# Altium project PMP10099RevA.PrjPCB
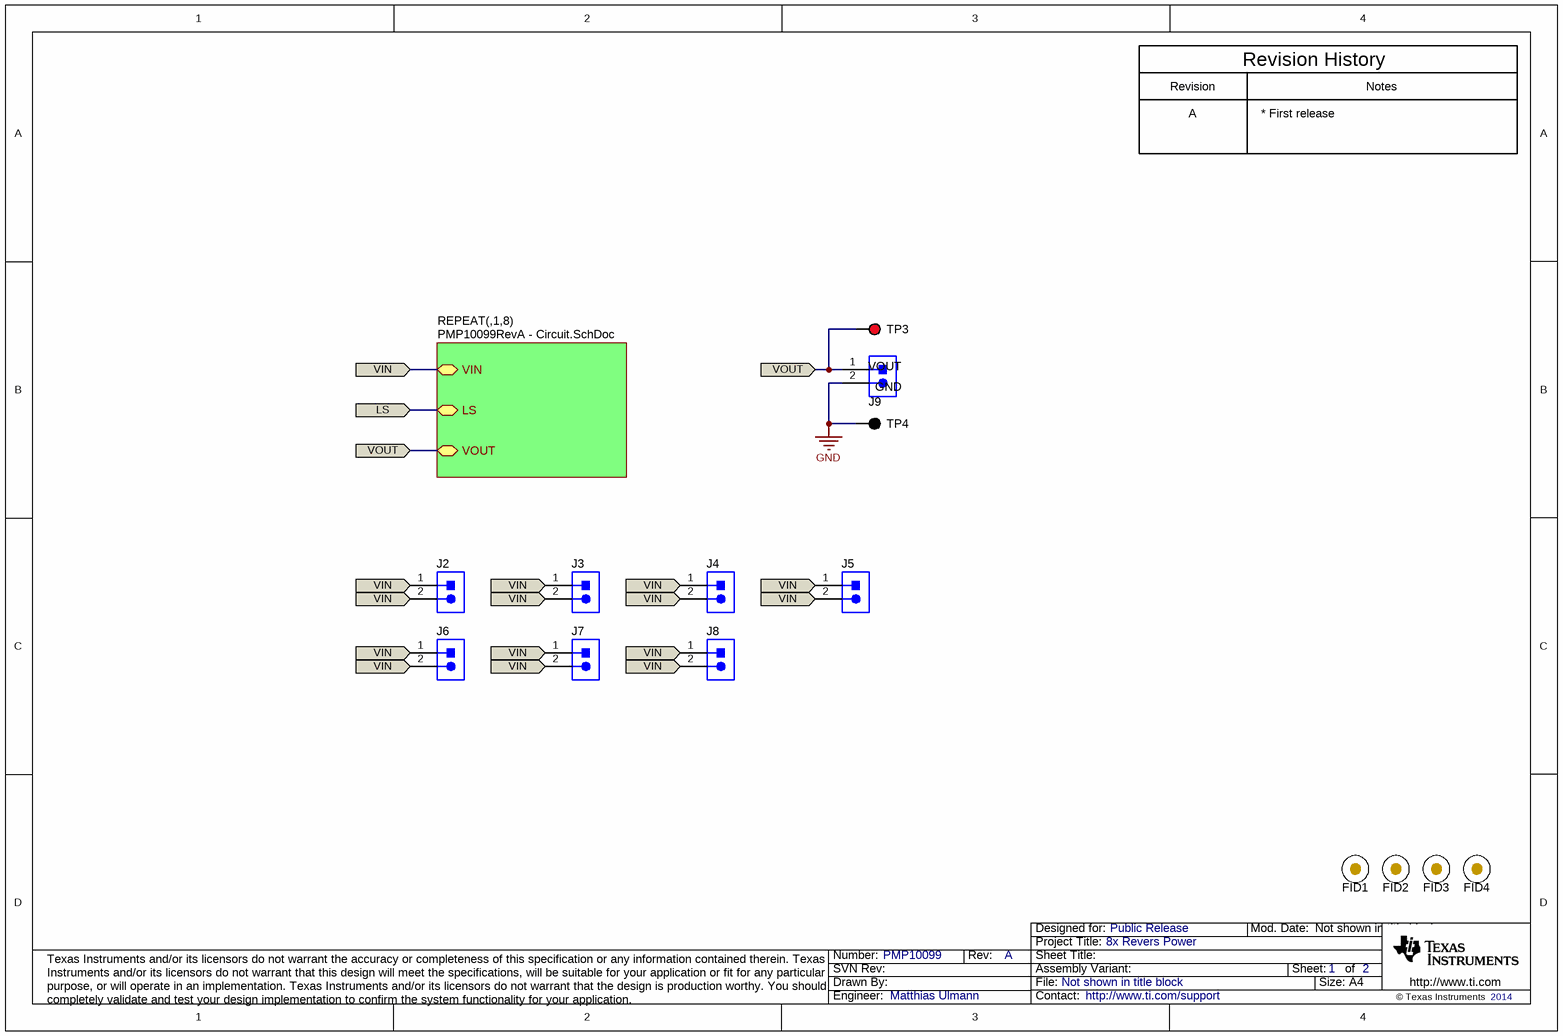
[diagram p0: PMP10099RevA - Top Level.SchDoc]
CopyrightYear: 2014; PCB_Layout: M. Ulmann; PCB_Rev: A; PRJ_Customer: Public Release; PRJ_Engineer: Matthias Ulmann; PRJ_Number: PMP10099; PRJ_Title: 8x Revers Power; SCH_Rev: A; TechSupport: http://www.ti.com/support
2 sheets, 558 parts. Net scope: hierarchical (ports join the sheet entries above them; power ports are global).
Board file: PMP10099RevA.PcbDoc
Sheets:
  PMP10099RevA - Top Level.SchDoc
    1 = PMP10099RevA - Circuit.SchDoc
    2 = PMP10099RevA - Circuit.SchDoc
    3 = PMP10099RevA - Circuit.SchDoc
    4 = PMP10099RevA - Circuit.SchDoc
    5 = PMP10099RevA - Circuit.SchDoc
    6 = PMP10099RevA - Circuit.SchDoc
    7 = PMP10099RevA - Circuit.SchDoc
    8 = PMP10099RevA - Circuit.SchDoc

## Sheet PMP10099RevA - Top Level.SchDoc
size A4; Date: Not shown in title block; ApprovedBy: Not shown in title block; CheckedBy: Not shown in title block; Author: Not shown in title block; CompanyName: Not shown in title block; Engineer: Not shown in title block; Organization: Not shown in title block; Address1: Not shown in title block; Address2: Not shown in title block; Address3: Not shown in title block; Address4: Not shown in title block; DocumentNumber: 1; Revision: Use project parameter SCH_Rev; SheetNumber: 1; SheetTotal: 2; PageSetup: Record=PageOptions|CenterHorizontal=True|CenterVertical=True|PrintScale=0.70|XCorrection=1.00|YCorrection=1.00|PrintKind=0|BorderSize=5000000|LeftOffset=0|BottomOffset=0|Orientation=2|PaperLength=1000|PaperWidth=1000|Scale=100|PaperSource=15|PrintQuality=600|MediaType=1|DitherType=10|PaperKind=A4|PrintScaleMode=1

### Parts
FID1  Fiducial  [Fiducial10-30]  (value not drawn)
FID2  Fiducial  [Fiducial10-30]  (value not drawn)
FID3  Fiducial  [Fiducial10-30]  (value not drawn)
FID4  Fiducial  [Fiducial10-30]  (value not drawn)
J2  PEC02SAAN  [CONN_PEC02SAAN]  (value not drawn)
J3  PEC02SAAN  [CONN_PEC02SAAN]  (value not drawn)
J4  PEC02SAAN  [CONN_PEC02SAAN]  (value not drawn)
J5  PEC02SAAN  [CONN_PEC02SAAN]  (value not drawn)
J6  PEC02SAAN  [CONN_PEC02SAAN]  (value not drawn)
J7  PEC02SAAN  [CONN_PEC02SAAN]  (value not drawn)
J8  PEC02SAAN  [CONN_PEC02SAAN]  (value not drawn)
J9  ED555/2DS  [TERM_BLK_ED555-2DS]  (value not drawn)
TP3  5000  [Keystone5000]  (value not drawn)
TP4  5001  [Keystone5001]  (value not drawn)

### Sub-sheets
REPEAT(,1,8) = PMP10099RevA - Circuit.SchDoc: VOUT, LS, VIN

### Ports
LS, VIN, VOUT

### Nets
GND: J9.2 TP4.1
LS: port LS, sheet REPEAT(,1,8)/LS
VIN: J2.1 J2.2 J3.1 J3.2 J4.1 J4.2 J5.1 J5.2 J6.1 J6.2 J7.1 J7.2 J8.1 J8.2 ; port VIN, sheet REPEAT(,1,8)/VIN
VOUT: J9.1 TP3.1 ; port VOUT, sheet REPEAT(,1,8)/VOUT

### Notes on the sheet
- Revision
- A
- * First release
- Revision History
- Notes
- VOUT
- GND

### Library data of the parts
FID1-FID4 = Fiducial: Fiducial mark.  There is nothing to buy or mount.; SymbolCreator: codlsc
J2-J8 = PEC02SAAN: Header, 100mil, 2x1, Tin, TH; Manufacturer: Sullins Connector Solutions; SymbolCreator: a0412235; U/M: EA
J9 = ED555/2DS: Terminal Block, 6A, 3.5mm Pitch, 2-Pos, TH; Manufacturer: On-Shore Technology; SymbolCreator: a0412235; CompType: Connector; U/M: EA
TP3 = 5000: Test Point, Miniature, Red, TH; Manufacturer: Keystone; CompType: Test Point Loop; U/M: EA
TP4 = 5001: Test Point, Miniature, Black, TH; Manufacturer: Keystone; CompType: Test Point Loop; U/M: EA

## Sheet PMP10099RevA - Circuit.SchDoc
size A3; Date: Not shown in title block; ApprovedBy: Not shown in title block; CheckedBy: Not shown in title block; Author: Not shown in title block; CompanyName: Not shown in title block; Engineer: Not shown in title block; Organization: Not shown in title block; Address1: Not shown in title block; Address2: Not shown in title block; Address3: Not shown in title block; Address4: Not shown in title block; DocumentNumber: 2; Revision: Use project parameter SCH_Rev; SheetNumber: 2; SheetTotal: 2; PageSetup: Record=PageOptions|CenterHorizontal=True|CenterVertical=True|PrintScale=0.70|XCorrection=1.00|YCorrection=1.00|PrintKind=0|BorderSize=5000000|LeftOffset=0|BottomOffset=0|Orientation=2|PaperLength=1000|PaperWidth=1000|Scale=100|PaperSource=15|PrintQuality=600|MediaType=1|DitherType=10|PaperKind=A4|PrintScaleMode=1
Used 8 times, as channels 1, 2, 3, 4, 5, 6, 7, 8. Parts and nets are listed once, with the designators drawn on the sheet.
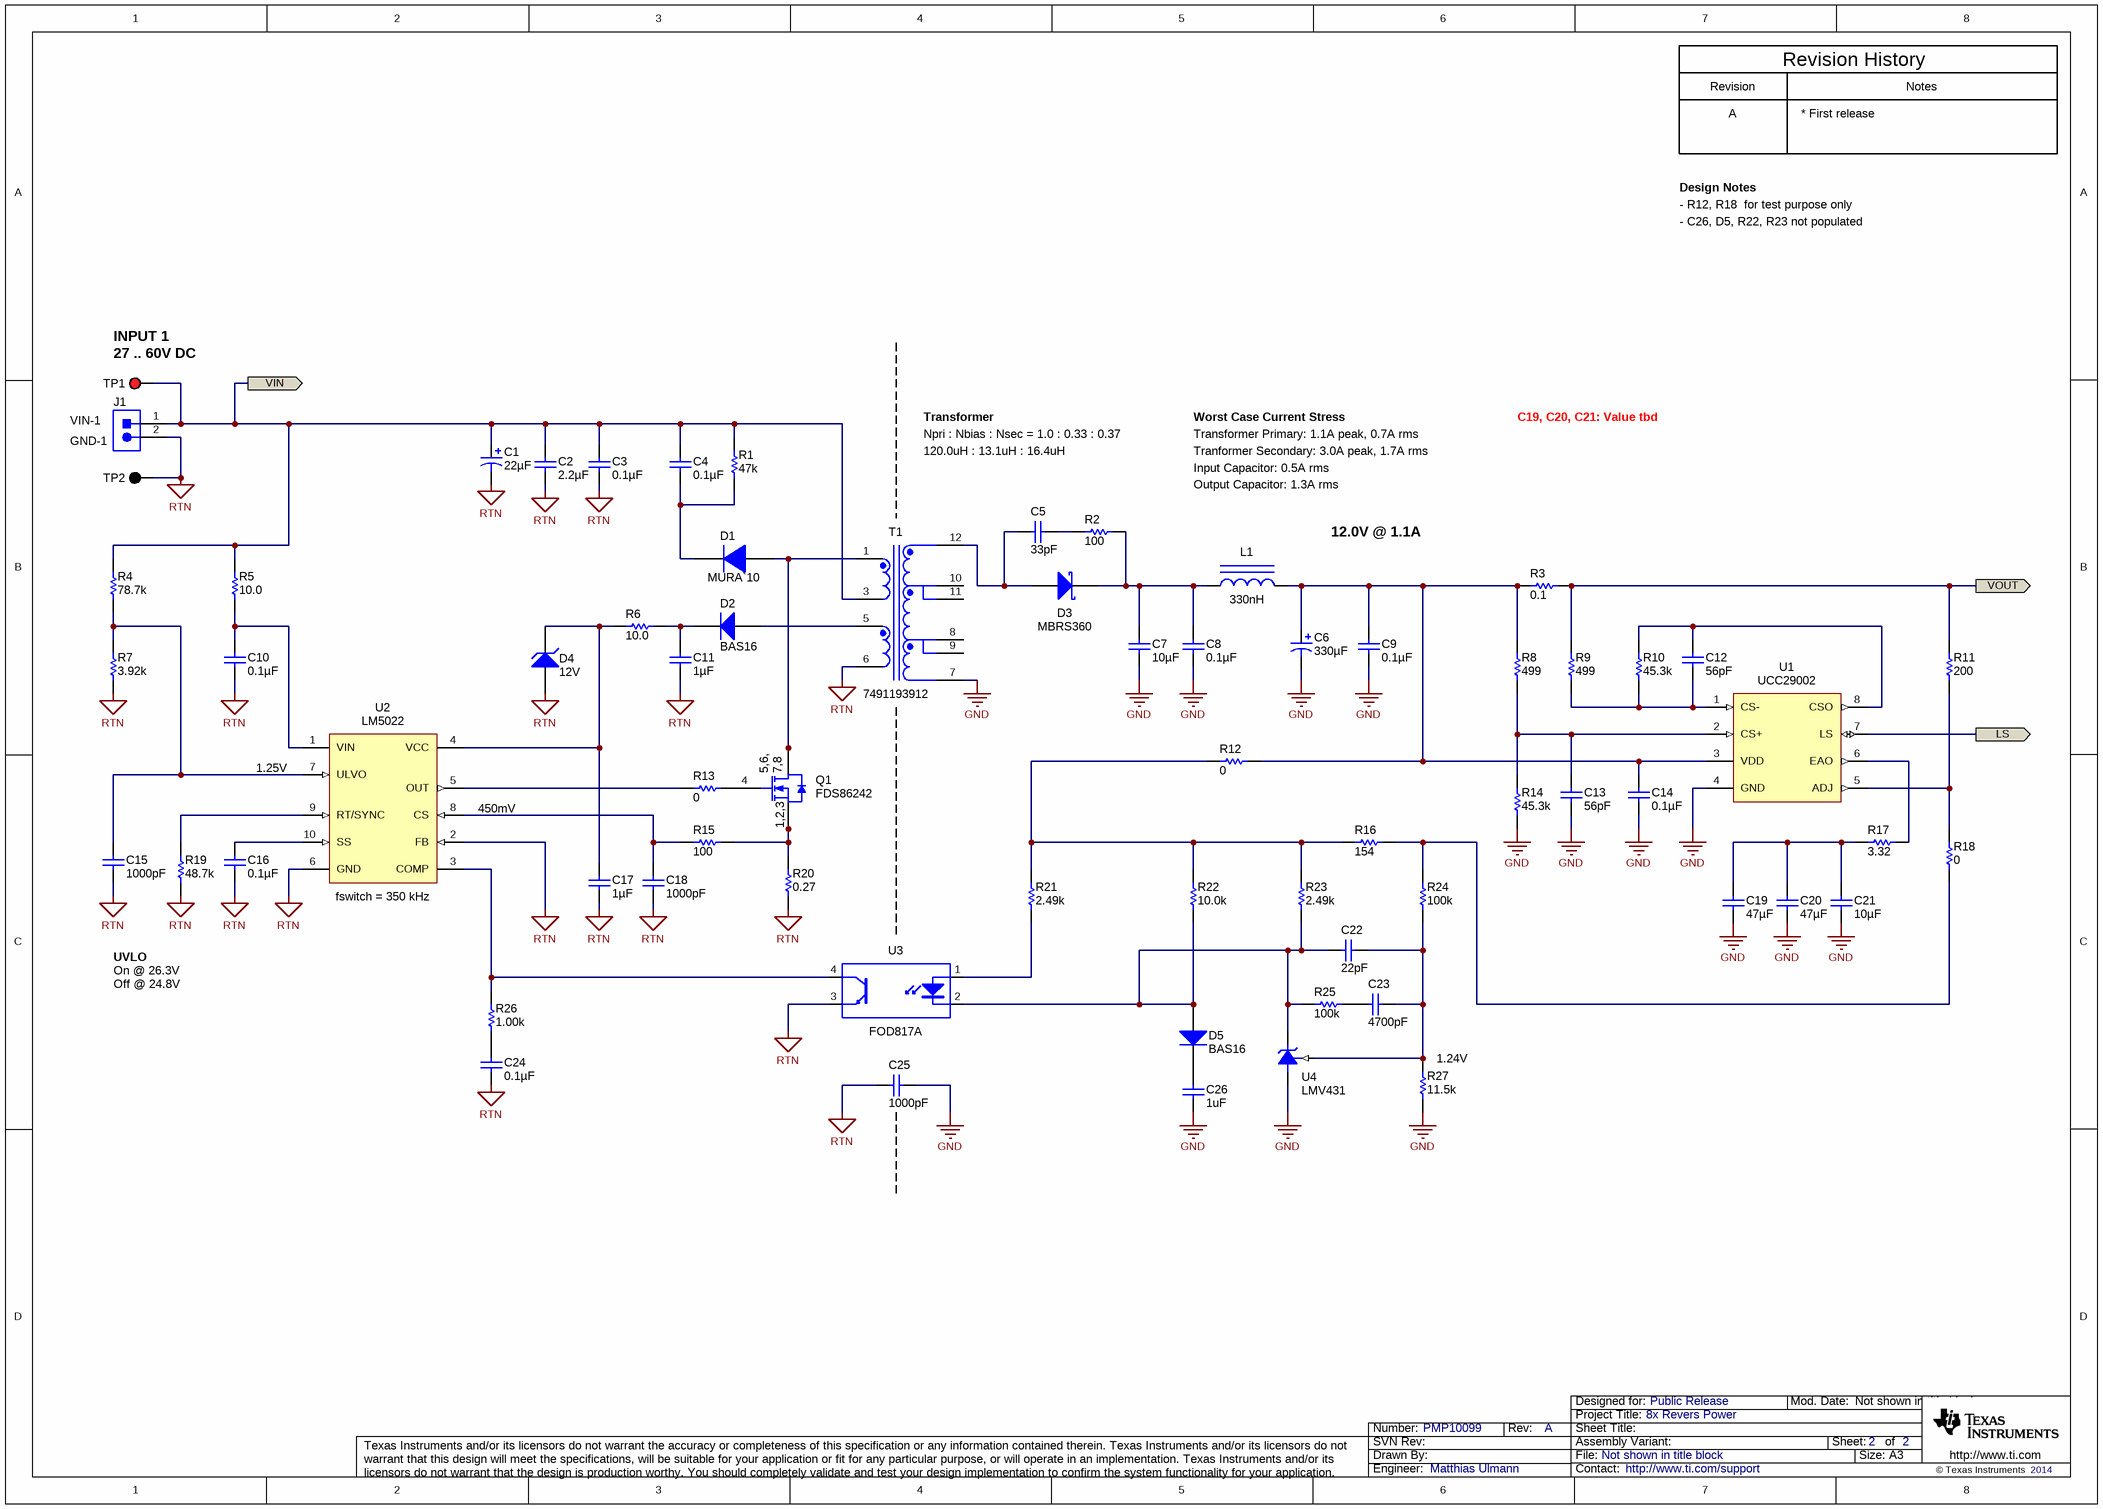
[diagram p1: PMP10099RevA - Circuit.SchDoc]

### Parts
C1  ValueDisplayed: 22µF  [SM_RADIAL_F]  (hidden comment: EEE-FK1K220P)
C2  ValueDisplayed: 2.2µF  [1210]  (hidden comment: GRM32ER72A225KA35L)
C3  ValueDisplayed: 0.1µF  [0603]  (hidden comment: GCM188R71H104KA57D)
C4  ValueDisplayed: 0.1µF  [0805_HV]  (hidden comment: HMK212B7104KG-T)
C5  ValueDisplayed: 33pF  [0805_HV]  (hidden comment: GRM2195C2A330JZ01D)
C6  ValueDisplayed: 330µF  [SM_RADIAL_F]  (hidden comment: EEE-FK1C331P)
C7  ValueDisplayed: 10µF  [1206]  (hidden comment: GRM31CR71E106KA12L)
C8  ValueDisplayed: 0.1µF  [0603]  (hidden comment: GCM188R71H104KA57D)
C9  ValueDisplayed: 0.1µF  [0603]  (hidden comment: GCM188R71H104KA57D)
C10  ValueDisplayed: 0.1µF  [0805_HV]  (hidden comment: HMK212B7104KG-T)
C11  ValueDisplayed: 1µF  [0603]  (hidden comment: GRM188R71E105KA12D)
C12  ValueDisplayed: 56pF  [0603]  (hidden comment: GRM1885C1H560JA01D)
C13  ValueDisplayed: 56pF  [0603]  (hidden comment: GRM1885C1H560JA01D)
C14  ValueDisplayed: 0.1µF  [0603]  (hidden comment: GCM188R71H104KA57D)
C15  ValueDisplayed: 1000pF  [0603]  (hidden comment: GRM188R71H102KA01D)
C16  ValueDisplayed: 0.1µF  [0603]  (hidden comment: GCM188R71H104KA57D)
C17  ValueDisplayed: 1µF  [0603]  (hidden comment: GRM188R71E105KA12D)
C18  ValueDisplayed: 1000pF  [0603]  (hidden comment: GRM188R71H102KA01D)
C19  ValueDisplayed: 47µF  [1210]  (hidden comment: GRM32ER70J476KE20L)
C20  ValueDisplayed: 47µF  [1210]  (hidden comment: GRM32ER70J476KE20L)
C21  ValueDisplayed: 10µF  [0805_140]  (hidden comment: GRM21BR71A106KE51K)
C22  ValueDisplayed: 22pF  [0603]  (hidden comment: GRM1885C1H220JA01D)
C23  ValueDisplayed: 4700pF  [0603]  (hidden comment: GRM188R71H472KA01D)
C24  ValueDisplayed: 0.1µF  [0603]  (hidden comment: GCM188R71H104KA57D)
C25  ValueDisplayed: 1000pF  [1812]  (hidden comment: 1812GC102KA1)
C26  ValueDisplayed: 1uF  [0603]  (hidden comment: GRM188R71E105KA12D)
D1  MURA`10  [SMA]
D2  BAS16  [SOT-23]
D3  MBRS360  [SMC]
D4  value 12V  [sod-323]  (hidden comment: BZX384-C12,115)
D5  BAS16  [SOT-23]
J1  ED555/2DS  [TERM_BLK_ED555-2DS]  (value not drawn)
L1  330nH  [WE-MAPI_3020]
Q1  FDS86242  [SOIC-8]
R1  ValueDisplayed: 47k  [1206]  (hidden comment: CRCW120647K0JNEA)
R2  value 100  [0805_HV]  (hidden comment: CRCW0805100RJNEA)
R3  ValueDisplayed: 0.1  [1206]  (hidden comment: ERJ-8RSJR10V)
R4  value 78.7k  [0805_HV]  (hidden comment: CRCW080578K7FKEA)
R5  value 10.0  [0805_HV]  (hidden comment: CRCW080510R0FKEA)
R6  ValueDisplayed: 10.0  [0603]  (hidden comment: CRCW060310R0FKEA)
R7  value 3.92k  [0805_HV]  (hidden comment: CRCW08053K92FKEA)
R8  ValueDisplayed: 499  [0603]  (hidden comment: CRCW0603499RFKEA)
R9  ValueDisplayed: 499  [0603]  (hidden comment: CRCW0603499RFKEA)
R10  ValueDisplayed: 45.3k  [0603]  (hidden comment: CRCW060345K3FKEA)
R11  ValueDisplayed: 200  [0603]  (hidden comment: CRCW0603200RFKEA)
R12  ValueDisplayed: 0  [0603]  (hidden comment: CRCW06030000Z0EA)
R13  ValueDisplayed: 0  [0603]  (hidden comment: CRCW06030000Z0EA)
R14  ValueDisplayed: 45.3k  [0603]  (hidden comment: CRCW060345K3FKEA)
R15  ValueDisplayed: 100  [0603]  (hidden comment: CRCW0603100RFKEA)
R16  ValueDisplayed: 154  [0603]  (hidden comment: CRCW0603154RFKEA)
R17  ValueDisplayed: 3.32  [0603]  (hidden comment: CRCW06033R32FKEA)
R18  ValueDisplayed: 0  [0603]  (hidden comment: CRCW06030000Z0EA)
R19  ValueDisplayed: 48.7k  [0603]  (hidden comment: CRCW060348K7FKEA)
R20  ValueDisplayed: 0.27  [1206]  (hidden comment: ERJ-8RQFR27V)
R21  ValueDisplayed: 2.49k  [0603]  (hidden comment: CRCW06032K49FKEA)
R22  ValueDisplayed: 10.0k  [0603]  (hidden comment: CRCW060310K0FKEA)
R23  ValueDisplayed: 2.49k  [0603]  (hidden comment: CRCW06032K49FKEA)
R24  ValueDisplayed: 100k  [0603]  (hidden comment: CRCW0603100KFKEA)
R25  ValueDisplayed: 100k  [0603]  (hidden comment: CRCW0603100KFKEA)
R26  ValueDisplayed: 1.00k  [0603]  (hidden comment: CRCW06031K00FKEA)
R27  ValueDisplayed: 11.5k  [0603]  (hidden comment: CRCW060311K5FKEA)
T1  7491193912  [WURTH_7491193912]
TP1  5000  [Keystone5000]  (value not drawn)
TP2  5001  [Keystone5001]  (value not drawn)
U1  UCC29002  [DGK0008A_N]
U2  LM5022  [MUB10A_N]
U3  FOD817A  [N04C]
U4  LMV431  [MF03A_N]

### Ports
LS, VIN, VOUT

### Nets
GND: C6.2(-) C7.2 C8.2 C9.2 C13.2 C14.2 C19.2 C20.2 C21.2 C25.1 C26.2 R14.1 R27.1 T1.7 U1.4(GND) U4.3(A)
RTN: C1.2(-) C2.2 C3.2 C10.2 C11.2 C15.2 C16.2 C17.2 C18.2 C24.2 C25.2 D4.2(A) J1.2 R7.1 R19.1 R20.1 T1.6 TP2.1 U2.2(FB) U2.6(GND) U3.3(E)
LS: U1.7(LS) ; port LS
VIN: C1.1(+) C2.1 C3.1 C4.1 J1.1 R1.2 R4.2 R5.2 T1.3 TP1.1 ; port VIN
VOUT: R3.2 R9.2 R11.2 ; port VOUT
NetC4_2: C4.2 D1.1(K) R1.1
NetC5_1: C5.1 R2.1
NetC5_2: C5.2 D3.2(A) T1.12
NetC6_1: C6.1(+) C9.1 C14.1 L1.2 R3.1 R8.2 R12.2 U1.3(VDD)
NetC7_1: C7.1 C8.1 D3.1(K) L1.1 R2.2
NetC10_1: C10.1 R5.1 U2.1(VIN)
NetC11_1: C11.1 D2.3(K) R6.2
NetC12_1: C12.1 R10.2 U1.8(CSO)
NetC12_2: C12.2 R9.1 R10.1 U1.1(CS-)
NetC13_1: C13.1 R8.1 R14.2 U1.2(CS+)
NetC15_1: C15.1 R4.1 R7.2 U2.7(ULVO)
NetC16_1: C16.1 U2.10(SS)
NetC17_1: C17.1 D4.1(K) R6.1 U2.4(VCC)
NetC18_1: C18.1 R15.1 U2.8(CS)
NetC19_1: C19.1 C20.1 C21.1 R17.1
NetC22_1: C22.1 D5.1(A) R22.2 R23.1 R25.2 U3.2(K) U4.2(K)
NetC22_2: C22.2 C23.2 R24.1 R27.2 U4.1(REF)
NetC23_1: C23.1 R25.1
NetC24_1: C24.1 R26.1
NetC26_1: C26.1 D5.3(K)
NetD1_2: D1.2(A) Q1.5(D) Q1.6(D) Q1.7(D) Q1.8(D) T1.1
NetD2_1: D2.1(A) T1.5
NetQ1_1: Q1.1(S) Q1.2(S) Q1.3(S) R15.2 R20.2
NetQ1_4: Q1.4(G) R13.2
NetR11_1: R11.1 R18.2 U1.5(ADJ)
NetR12_1: R12.1 R16.1 R21.2 R22.1 R23.2
NetR13_1: R13.1 U2.5(OUT)
NetR16_2: R16.2 R18.1 R24.2
NetR17_2: R17.2 U1.6(EAO)
NetR19_2: R19.2 U2.9(RT/SYNC)
NetR21_1: R21.1 U3.1(A)
NetR26_2: R26.2 U2.3(COMP) U3.4(C)

Not connected (* = marked no-connect by the designer): T1 8 9 10 11

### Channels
1: designators end in _A; ports LS=LS VIN=VIN VOUT=VOUT
2: designators end in _B; ports LS=LS VIN=VIN VOUT=VOUT
3: designators end in _C; ports LS=LS VIN=VIN VOUT=VOUT
4: designators end in _D; ports LS=LS VIN=VIN VOUT=VOUT
5: designators end in _E; ports LS=LS VIN=VIN VOUT=VOUT
6: designators end in _F; ports LS=LS VIN=VIN VOUT=VOUT
7: designators end in _G; ports LS=LS VIN=VIN VOUT=VOUT
8: designators end in _H; ports LS=LS VIN=VIN VOUT=VOUT

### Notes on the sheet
- Revision
- A
- * First release
- Revision History
- Notes
- Design Notes
- - R12, R18  for test purpose only
- - C26, D5, R22, R23 not populated
- (near TP1) INPUT 1
- (near TP1) 27 .. 60V DC
- VIN-1
- GND-1
- Transformer
- Npri : Nbias : Nsec = 1.0 : 0.33 : 0.37
- 120.0uH : 13.1uH : 16.4uH
- Worst Case Current Stress
- Transformer Primary: 1.1A peak, 0.7A rms
- Tranformer Secondary: 3.0A peak, 1.7A rms
- C19, C20, C21: Value tbd
- Input Capacitor: 0.5A rms
- Output Capacitor: 1.3A rms
- 12.0V @ 1.1A
- (near U2) 1.25V
- (near U2) 450mV
- (near U2) fswitch = 350 kHz
- On @ 26.3V
- Off @ 24.8V
- UVLO
- (near R27) 1.24V

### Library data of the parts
C1 = EEE-FK1K220P: CAP, AL, 22 µF, 80 V, +/- 20%, 1.3 ohm, SMD; Manufacturer: Panasonic; Polarized: Y; CompType: Capacitor; Value: 22uF; U/M: EA; Cap_F: 0.000022; Tolerance_%: 20; Value1: 1.3 ohm; VDC_V: 80; Value2: 80V; ESR_ohm: 1.3; IRMS_A: 0.13; TaMin_C: -55; TaMax_C: 105; Cap_Case: F
C2 = GRM32ER72A225KA35L: CAP, CERM, 2.2 µF, 100 V, +/- 10%, X7R, 1210; Manufacturer: MuRata; Polarized: N; CompType: Capacitor; Value: 2.2uF; U/M: EA; Cap_F: 0.0000022; Tolerance_%: 10; ESR_ohm: 0.007; Value1: 0.007 ohm; VDC_V: 100; Value2: 100V; IRMS_A: 4.4; TaMin_C: -55; TaMax_C: 125
C3 C8 C9 C14 C16 C24 = GCM188R71H104KA57D: CAP, CERM, 0.1 µF, 50 V, +/- 10%, X7R, 0603; Manufacturer: MuRata; Polarized: N; CompType: Capacitor; Value: 0.1uF; U/M: EA; Cap_F: 0.0000001; Tolerance_%: 10; ESR_ohm: 0.02; Value1: 0.02 ohm; VDC_V: 50; Value2: 50V; IRMS_A: 1.84; TaMin_C: -55; TaMax_C: 125
C4 C10 = HMK212B7104KG-T: CAP, CERM, 0.1 µF, 100 V, +/- 10%, X7R, 0805; Manufacturer: Taiyo Yuden; Polarized: N; CompType: Capacitor; Value: 0.1uF; U/M: EA; Cap_F: 0.0000001; Tolerance_%: 10; Value1: Unknown; VDC_V: 100; Value2: 100V; TaMin_C: -55; TaMax_C: 125; Cap_Case: 0805
C5 = GRM2195C2A330JZ01D: CAP, CERM, 33 pF, 100 V, +/- 5%, C0G/NP0, 0805; Manufacturer: MuRata; Polarized: N; CompType: Capacitor; Value: 33pF; U/M: EA; Cap_F: 0.000000000033; Tolerance_%: 5; Value1: Unknown; VDC_V: 100; Value2: 100V; TaMin_C: -55; TaMax_C: 125; Cap_Case: 0805
C6 = EEE-FK1C331P: CAP, AL, 330 µF, 16 V, +/- 20%, 0.16 ohm, SMD; Manufacturer: Panasonic; Polarized: Y; CompType: Capacitor; Value: 330uF; U/M: EA; Cap_F: 0.00033; Tolerance_%: 20; VDC_V: 16; Value2: 16V; ESR_ohm: 0.16; IRMS_A: 0.6; TaMin_C: -55; TaMax_C: 105; Cap_Case: F
C7 = GRM31CR71E106KA12L: CAP, CERM, 10 µF, 25 V, +/- 10%, X7R, 1206; Manufacturer: MuRata; Polarized: N; CompType: Capacitor; Value: 10uF; U/M: EA; Cap_F: 0.00001; Tolerance_%: 10; Value1: Unknown; VDC_V: 25; Value2: 25V; TaMin_C: -55; TaMax_C: 125; Cap_Case: 2220
C11 C17 C26 = GRM188R71E105KA12D: CAP, CERM, 1 µF, 25 V, +/- 10%, X7R, 0603; Manufacturer: MuRata; Polarized: N; CompType: Capacitor; Value: 1uF; U/M: EA; Cap_F: 0.000001; Tolerance_%: 10; Value1: Unknown; VDC_V: 25; Value2: 25V; TaMin_C: -55; TaMax_C: 125
C12 C13 = GRM1885C1H560JA01D: CAP, CERM, 56 pF, 50 V, +/- 5%, C0G/NP0, 0603; Manufacturer: MuRata; Polarized: N; CompType: Capacitor; Value: 56pF; U/M: EA; Cap_F: 0.000000000056; Tolerance_%: 5; Value1: Unknown; VDC_V: 50; Value2: 50V; TaMin_C: -55; TaMax_C: 125
C15 C18 = GRM188R71H102KA01D: CAP, CERM, 1000 pF, 50 V, +/- 10%, X7R, 0603; Manufacturer: MuRata; Polarized: N; CompType: Capacitor; Value: 1000pF; U/M: EA; Cap_F: 0.000000001; Tolerance_%: 10; Value1: Unknown; VDC_V: 50; Value2: 50V; TaMin_C: -55; TaMax_C: 125
C19 C20 = GRM32ER70J476KE20L: CAP, CERM, 47 µF, 6.3 V, +/- 10%, X7R, 1210; Manufacturer: MuRata; Polarized: N; CompType: Capacitor; Value: 47uF; U/M: EA; Cap_F: 0.000047; Tolerance_%: 10; Value1: Unknown; VDC_V: 6.3; Value2: 6.3V; TaMin_C: -55; TaMax_C: 125
C21 = GRM21BR71A106KE51K: CAP, CERM, 10 µF, 10 V, +/- 10%, X7R, 0805_140; Manufacturer: MuRata; Polarized: N; CompType: Capacitor; Value: 10uF; U/M: EA; Cap_F: 0.00001; Tolerance_%: 10; Value1: Unknown; Value2: 10V; TaMin_C: -55; TaMax_C: 125; Cap_Case: 0805
C22 = GRM1885C1H220JA01D: CAP, CERM, 22 pF, 50 V, +/- 5%, C0G/NP0, 0603; Manufacturer: MuRata; Polarized: N; CompType: Capacitor; Value: 22pF; U/M: EA; Cap_F: 0.000000000022; Tolerance_%: 5; Value1: Unknown; VDC_V: 50; Value2: 50V; TaMin_C: -55; TaMax_C: 125
C23 = GRM188R71H472KA01D: CAP, CERM, 4700 pF, 50 V, +/- 10%, X7R, 0603; Manufacturer: MuRata; Polarized: N; CompType: Capacitor; Value: 4700pF; U/M: EA; Cap_F: 0.0000000047; Tolerance_%: 10; Value1: Unknown; VDC_V: 50; Value2: 50V; TaMin_C: -55; TaMax_C: 125
C25 = 1812GC102KA1: CAP, CERM, 1000 pF, 2000 V, +/- 10%, X7R, 1812; Manufacturer: AVX; Polarized: N; CompType: Capacitor; Value: 1000pF; U/M: EA; Cap_F: 0.000000001; Tolerance_%: 10; Value1: Unknown; VDC_V: 2000; Value2: 2000V; TaMin_C: -55; TaMax_C: 125
D1 = MURA120T3G: Diode, Ultrafast, 200 V, 1 A, SMA; Manufacturer: ON Semiconductor; U/M: EA; Vf_V: 0.0875; Value: 200V; Value1: 1A; Value2: 0.0875V; Io_A: 1; Vr_V: 200; TJmax_C: 175
D2 D5 = BAS16-7-F: Diode, Ultrafast, 75 V, 0.3 A, SOT-23; Manufacturer: Diodes Inc.; U/M: EA; Vf_V: 1.125; Value: 75V; Value1: 0.3A; Value2: 1.125V; Io_A: 0.3; Vr_V: 75
D3 = MBRS340T3G: Diode, Schottky, 60 V, 3 A, SMC; PartNumber: MBRS360T3G; Manufacturer: ON Semiconductor; U/M: EA; Vf_V: 0.525; Value: 60V; Value1: 3A; Value2: 0.525V; Io_A: 3; Vr_V: 60; TJmax_C: 125; RJC_CperW: 11
D4 = BZX384-C12,115: Diode, Zener, 12 V, 300 mW, SOD-323; Manufacturer: NXP Semiconductor; SymbolCreator: a0412235; U/M: EA; Power_W: 0.3; Vz_V: 12; Value1: 0.3W; RJA_CperW: 415
J1 = ED555/2DS: as J9 on sheet PMP10099RevA - Top Level
L1 = 744383360033: Inductor, 330 nH, 5.5 A, 0.014 ohm, SMD; Manufacturer: Wurth Elektronik eiSos; Ind_H: 330.0E-9; Imax_A: 5.5; Irms: 5.5A @ 40C rise; Isat: 8.3A @ 20% inductance drop; DCR_ohm: 0.014; Value2: 5.5A
Q1 = FDS86242: MOSFET, N-CH, 150 V, 4.1 A, SOIC-8; Manufacturer: Fairchild Semiconductor; Alternate Manufacturer: None; U/M: EA; ChType: N; Value: 150V; VdsMax_V: 150; Value1: 0.067 ohm; Rdson45_ohm: 0.067; Value2: 13 nC; QgTyp_nC: 13; Vgs_V: 4; IdsMax_A: 4.1
R1 = CRCW120647K0JNEA: RES, 47 k, 5%, 0.25 W, 1206; Manufacturer: Vishay-Dale; CompType: Resistor; Value: 47k; Res_ohm: 47000; Value_Code: 47k0; Tolerance_%: 5; Power_W: 0.25; Value2: 0.25W; VDC_V: 200; TempCo: 200 ppm/C; EIA_Code: E24; U/M: EA
R2 = CRCW0805100RJNEA: RES, 100 ohm, 5%, 0.125W, 0805; Manufacturer: Vishay-Dale; CompType: Resistor; Value_Code: 100R; Tolerance_%: 5; Power_W: 0.125; VDC_V: 150; TempCo: 200 ppm/C; EIA_Code: E24; U/M: EA
R3 = ERJ-8RSJR10V: RES, 0.1, 5%, 0.25 W, 1206; Manufacturer: Panasonic; CompType: Resistor; Value: 0.1; Value_Code: R100; Tolerance_%: 5; Power_W: 0.25; Value2: 0.25W; TempCo: 250 ppm/C; EIA_Code: E24; U/M: EA
R4 = CRCW080578K7FKEA: RES, 78.7k ohm, 1%, 0.125W, 0805; Manufacturer: Vishay-Dale; CompType: Resistor; Res_ohm: 78700; Value_Code: 78k7; Tolerance_%: 1; Power_W: 0.125; VDC_V: 150; TempCo: 100 ppm/C; EIA_Code: E96; U/M: EA
R5 = CRCW080510R0FKEA: RES, 10.0 ohm, 1%, 0.125W, 0805; Manufacturer: Vishay-Dale; CompType: Resistor; Res_ohm: 10; Value_Code: 10R0; Tolerance_%: 1; Power_W: 0.125; VDC_V: 150; TempCo: 100 ppm/C; EIA_Code: E96; U/M: EA
R6 = CRCW060310R0FKEA: RES, 10.0, 1%, 0.1 W, 0603; Manufacturer: Vishay-Dale; CompType: Resistor; Value: 10.0; Res_ohm: 10; Value_Code: 10R0; Tolerance_%: 1; Power_W: 0.1; Value2: 0.1W; VDC_V: 75; TempCo: 100 ppm/C; EIA_Code: E96; U/M: EA
R7 = CRCW08053K92FKEA: RES, 3.92k ohm, 1%, 0.125W, 0805; Manufacturer: Vishay-Dale; CompType: Resistor; Res_ohm: 3920; Value_Code: 3k92; Tolerance_%: 1; Power_W: 0.125; VDC_V: 150; TempCo: 100 ppm/C; EIA_Code: E96; U/M: EA
R8 R9 = CRCW0603499RFKEA: RES, 499, 1%, 0.1 W, 0603; Manufacturer: Vishay-Dale; CompType: Resistor; Value: 499; Value_Code: 499R; Tolerance_%: 1; Power_W: 0.1; Value2: 0.1W; VDC_V: 75; TempCo: 100 ppm/C; EIA_Code: E96; U/M: EA
R10 R14 = CRCW060345K3FKEA: RES, 45.3 k, 1%, 0.1 W, 0603; Manufacturer: Vishay-Dale; CompType: Resistor; Value: 45.3k; Res_ohm: 45300; Value_Code: 45k3; Tolerance_%: 1; Power_W: 0.1; Value2: 0.1W; VDC_V: 75; TempCo: 100 ppm/C; EIA_Code: E96; U/M: EA
R11 = CRCW0603200RFKEA: RES, 200, 1%, 0.1 W, 0603; Manufacturer: Vishay-Dale; CompType: Resistor; Value: 200; Value_Code: 200R; Tolerance_%: 1; Power_W: 0.1; Value2: 0.1W; VDC_V: 75; TempCo: 100 ppm/C; EIA_Code: E96; U/M: EA
R12 R13 R18 = CRCW06030000Z0EA: RES, 0, 5%, 0.1 W, 0603; Manufacturer: Vishay-Dale; CompType: Resistor; Value: 0; Value_Code: 0000; Tolerance_%: 5; Power_W: 0.1; Value2: 0.1W; VDC_V: 75; TempCo: 200 ppm/C; EIA_Code: E24; U/M: EA
R15 = CRCW0603100RFKEA: RES, 100, 1%, 0.1 W, 0603; Manufacturer: Vishay-Dale; CompType: Resistor; Value: 100; Value_Code: 100R; Tolerance_%: 1; Power_W: 0.1; Value2: 0.1W; VDC_V: 75; TempCo: 100 ppm/C; EIA_Code: E96; U/M: EA
R16 = CRCW0603154RFKEA: RES, 154, 1%, 0.1 W, 0603; Manufacturer: Vishay-Dale; CompType: Resistor; Value: 154; Value_Code: 154R; Tolerance_%: 1; Power_W: 0.1; Value2: 0.1W; VDC_V: 75; TempCo: 100 ppm/C; EIA_Code: E96; U/M: EA
R17 = CRCW06033R32FKEA: RES, 3.32, 1%, 0.1 W, 0603; Manufacturer: Vishay-Dale; CompType: Resistor; Value: 3.32; Value_Code: 3R32; Tolerance_%: 1; Power_W: 0.1; Value2: 0.1W; VDC_V: 75; TempCo: 100 ppm/C; EIA_Code: E96; U/M: EA
R19 = CRCW060348K7FKEA: RES, 48.7 k, 1%, 0.1 W, 0603; Manufacturer: Vishay-Dale; CompType: Resistor; Value: 48.7k; Res_ohm: 48700; Value_Code: 48k7; Tolerance_%: 1; Power_W: 0.1; Value2: 0.1W; VDC_V: 75; TempCo: 100 ppm/C; EIA_Code: E96; U/M: EA
R20 = ERJ-8RQFR27V: RES, 0.27, 1%, 0.25 W, 1206; Manufacturer: Panasonic; CompType: Resistor; Value: 0.27; Value_Code: R270; Tolerance_%: 1; Power_W: 0.25; Value2: 0.25W; TempCo: 250 ppm/C; EIA_Code: E96; U/M: EA
R21 R23 = CRCW06032K49FKEA: RES, 2.49 k, 1%, 0.1 W, 0603; Manufacturer: Vishay-Dale; CompType: Resistor; Value: 2.49k; Res_ohm: 2490; Value_Code: 2k49; Tolerance_%: 1; Power_W: 0.1; Value2: 0.1W; VDC_V: 75; TempCo: 100 ppm/C; EIA_Code: E96; U/M: EA
R22 = CRCW060310K0FKEA: RES, 10.0 k, 1%, 0.1 W, 0603; Manufacturer: Vishay-Dale; CompType: Resistor; Value: 10.0k; Res_ohm: 10000; Value_Code: 10k0; Tolerance_%: 1; Power_W: 0.1; Value2: 0.1W; VDC_V: 75; TempCo: 100 ppm/C; EIA_Code: E96; U/M: EA
R24 R25 = CRCW0603100KFKEA: RES, 100 k, 1%, 0.1 W, 0603; Manufacturer: Vishay-Dale; CompType: Resistor; Value: 100k; Res_ohm: 100000; Tolerance_%: 1; Power_W: 0.1; Value2: 0.1W; VDC_V: 75; TempCo: 100 ppm/C; EIA_Code: E96; U/M: EA
R26 = CRCW06031K00FKEA: RES, 1.00 k, 1%, 0.1 W, 0603; Manufacturer: Vishay-Dale; CompType: Resistor; Value: 1.00k; Res_ohm: 1000; Value_Code: 1k00; Tolerance_%: 1; Power_W: 0.1; Value2: 0.1W; VDC_V: 75; TempCo: 100 ppm/C; EIA_Code: E96; U/M: EA
R27 = CRCW060311K5FKEA: RES, 11.5 k, 1%, 0.1 W, 0603; Manufacturer: Vishay-Dale; CompType: Resistor; Value: 11.5k; Res_ohm: 11500; Value_Code: 11k5; Tolerance_%: 1; Power_W: 0.1; Value2: 0.1W; VDC_V: 75; TempCo: 100 ppm/C; EIA_Code: E96; U/M: EA
T1 = 7491193912: Transformer, 120 uH, SMT; Manufacturer: Wurth Elektronik eiSos; SymbolCreator: Altium; DCR_Ohm: 0.22; Value: 120 uH; LeakageL: 1.5 uH; U/M: EA
TP1 = 5000: as TP3 on sheet PMP10099RevA - Top Level
TP2 = 5001: as TP4 on sheet PMP10099RevA - Top Level
U1 = UCC29002DGK: ADVANCED 8-PIN LOAD SHARE CONTROLLER, DGK0008A; Alternate Manufacturer: None; Manufacturer: Texas Instruments; SymbolCreator: a0411947; CompType: IC; U/M: EA
U2 = LM5022MM: 60V Low Side Controller for Boost and SEPIC, 10-pin MSOP; Manufacturer: Texas Instruments; PackageTopMarking: ZXTT*5022; PowerWise: Y; CompType: Switcher
U3 = FOD817DS: Optocoupler, 5kV RMS, SMT; Manufacturer: Fairchild Semiconductor; U/M: EA
U4 = LMV431AIMF: Low-Voltage (1.24V) Adjustable Precision Shunt Regulator, 3-pin SOT-23; Manufacturer: Texas Instruments; PackageTopMarking: RLA*XTT; PowerWise: N; CompType: MiscPower

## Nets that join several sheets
GND: PMP10099RevA - Top Level (J9.2 TP4.1), 1 (16 pins), 2 (16 pins), 3 (16 pins), 4 (16 pins), 5 (16 pins), 6 (16 pins), 7 (16 pins), 8 (16 pins)
RTN: 1 (21 pins), 2 (21 pins), 3 (21 pins), 4 (21 pins), 5 (21 pins), 6 (21 pins), 7 (21 pins), 8 (21 pins)
LS: 1 (U1_A.7), 2 (U1_B.7), 3 (U1_C.7), 4 (U1_D.7), 5 (U1_E.7), 6 (U1_F.7), 7 (U1_G.7), 8 (U1_H.7)
VIN: PMP10099RevA - Top Level (14 pins), 1 (10 pins), 2 (10 pins), 3 (10 pins), 4 (10 pins), 5 (10 pins), 6 (10 pins), 7 (10 pins), 8 (10 pins)
VOUT: PMP10099RevA - Top Level (J9.1 TP3.1), 1 (R3_A.2 R9_A.2 R11_A.2), 2 (R3_B.2 R9_B.2 R11_B.2), 3 (R3_C.2 R9_C.2 R11_C.2), 4 (R3_D.2 R9_D.2 R11_D.2), 5 (R3_E.2 R9_E.2 R11_E.2), 6 (R3_F.2 R9_F.2 R11_F.2), 7 (R3_G.2 R9_G.2 R11_G.2), 8 (R3_H.2 R9_H.2 R11_H.2)

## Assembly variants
001: all parts fitted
